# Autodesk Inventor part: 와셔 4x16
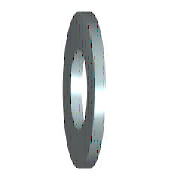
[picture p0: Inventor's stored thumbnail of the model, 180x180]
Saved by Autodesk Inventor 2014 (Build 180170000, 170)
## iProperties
IsCustomPart: 1
Created: 2012-02
Part Number: 와셔 4x16
Material: 강철, 연강
Description: 미터법 평면 와셔
Document SubType Name: Modeling
Standard: ANSI B18.22M
Designer: mduedu
Standard Revision: 1999
Standards Organization: ANSI
Language: ko-KR
Size Designation: 4 W
Categories: <MemberInstance><Categories><Category DisplayName="조임쇠" InternalName="e4da775c-781d-43d5-af7c-5136215cf5a6" Mnemonic="FSTN"><Category DisplayName="와셔" InternalN
Density: 1 g/cm^3
Appearance: Blue - Wall Paint - Glossy
Author: mduedu
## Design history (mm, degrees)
sketch "스케치"
  geometry: C1 r 8 at (0, 0); C2 r 2.35 at (0, 0); 1 further point
  constraints: 2 centre point, 2 coincident
  dimensions: "d0" = 4.7 diameter of C2 (= SD1); "d1" = 16 diameter of C1 (= SD2)
extrude "본체" new body sketch "스케치" distance "d2" = 2.3 (= SD); taper "d3" = 0 deg
workaxis "Work Axis1"
workplane "Work Plane1"
body "Solid1"
other parameters: "SD1" = 4.7 [user parameter; used in 1 equation term], "SD2" = 16 [user parameter; used in 1 equation term], "SD" = 2.3 [user parameter; used in 1 equation term], "d4" = 0, "d5" = 0, "d6" = 0, "d7" = 0, "NND" = 4 [user parameter]
